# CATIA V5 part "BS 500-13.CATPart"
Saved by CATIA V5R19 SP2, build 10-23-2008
Part number: BS 500-13
Bounding box of the stored display mesh (mm): x -18.951 to 18.951, y -18.952 to 18.952, z 0 to 56
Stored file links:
  C:\Users\Bora\Desktop\3D Katı model\BS serisi\BS 500\BS 500-13.CATPart
  C:\Program Files\Dassault Systemes\B19\intel_a\reffiles\standard\MetricThickPitch.txt
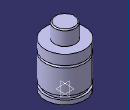
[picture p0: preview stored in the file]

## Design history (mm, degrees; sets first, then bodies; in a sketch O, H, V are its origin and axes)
Body1 (main body)
  Sketch1 on yz-plane, origin (0, 0, 0), H (0, 1, 0), V (0, 0, 1)
    point P1 (10, 55)
    point P3 (10, 55)
    point P5 (19, 32.5)
    point P6 (19, 30.5)
    point P9 (19, 32.5)
    point P14 (19, 30.5)
    line L1 (10, 55) -> (10, 42)
    arc A1 centre (9, 55) radius 1 from (10, 55) to (9, 56) ccw
    arc A2 centre (19, 31.5) radius 1 from (19, 32.5) to (19, 30.5) ccw
    line L2 (19, 0) -> (19, 4)
    line L3 (19, 32.5) -> (19, 42)
    line L4 (17, 7.5) -> (17, 4)
    line L5 (19, 7.5) -> (19, 30.5)
    line L6 (9, 56) -> (0, 56)
    point P15 (0, 56)
    line L7 (10, 42) -> (19, 42)
    line L8 (0, 0) -> (19, 0)
    line L9 (17, 7.5) -> (19, 7.5)
    line L10 (17, 4) -> (19, 4)
    coincidence: P15 V, P1 P3, P5 P9, P6 P14
    tangency: L6 A1
    horizontal: L7 H, L8 H, L9 H, L10 H
  Shaft1: profile Sketch1, axis Sketch1.V, angle 360
  Sketch2 on face of Shaft1 from Sketch1.L8, origin (0, 0, 0), H (1, 0, 0), V (0, -1, 0)
    point P1 (0, 0)
  Hole1: placed by Sketch2, at (0, 0, 0) direction (0, 0, 1), diameter 6.647, depth 4, threaded "M8", thread diameter 8, thread depth 4, pitch 1.25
